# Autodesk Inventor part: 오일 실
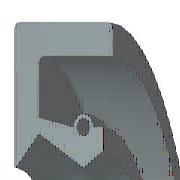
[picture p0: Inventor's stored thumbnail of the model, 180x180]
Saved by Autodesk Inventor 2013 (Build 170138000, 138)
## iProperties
IsCustomPart: 0
Created: 2009-02
Part Number: 오일 실
Material: 고무
Description: 오일-실
Document SubType Name: Modeling
Standard: KS B 2804
Designer: KYOUNG IL JANG
Standards Organization: KS
Language: ko-KR
Size Designation: D - 20 32 8
Categories: <MemberInstance><Categories><Category DisplayName="샤프트 부품" InternalName="7f7aeb1f-a693-4053-b835-cee3144e0d98" Mnemonic="SHFT"><Category DisplayName="실링" Intern
Density: 0.93 g/cm^3
Mass: 2.19344 g
Surface Area: 31.4782 cm^2
Volume: 2.35853 cm^3
Author: KYOUNG IL JANG
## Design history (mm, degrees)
revolve "본체" stored, may be unused: angle "d17" = 90 deg
revolve "스프링1" stored, may be unused: angle "d18" = 90 deg
body "Solid1"
sketch "스케치1"
  geometry: L1 (0, 16)-(8, 16); L2 (8, 14.25)-(1.75, 14.25); L3 (1.75, 11.75)-(4.9, 10); L4 (4.9, 10)-(0, 10); L5 (0, 0)-(9.586, 0) reference; L6 (4.9, 10)-(6.3, 10.875); L7 (0, 18)-(0, -3) reference; L8 (-1.941, 0)-(11.507, 0) reference; L9 (4.2, 12.1)-(1.75, 12.71); L10 (1.75, 12.71)-(1.75, 14.25); L11 (0, 16)-(0, 10.088); L12 (4.9, 10)-(0, 10); L13 (1.75, 11.75)-(0.152, 10.028); L14 (8, 16)-(8, 14.25); L15 (5.6, 12.1)-(6.3, 12.1); L16 (6.3, 12.1)-(6.3, 10.875); C1 r 0.455 at (4.9, 12.1); A1 r 0.7 centre (4.9, 12.1) between (5.6, 12.1) and (4.2, 12.1); A2 r 0.088 centre (0.088, 10.088) between (0, 10.088) and (0.152, 10.028); 1 further point
  constraints: 28 end point, 5 horizontal alignment, 5 point on line, 4 point on circle, 4 vertical alignment, 3 centre point, 3 tangent, 2 collinear, 2 horizontal, 2 perpendicular, 1 coincident, 1 parallel
  dimensions: "d0" = 32 diameter of L1 L5 (= SD2); "d1" = 1.75 distance of L1.end L2.start (= SD); "d2" = 0.91 diameter of C1 (= SPDI); "d3" = 1.4 diameter of A1 (= SPDA); "d4" = 20 diameter of L3.end L5 (= NND); "d5" = 23.5 diameter of L3.start L5 (= TKDM); "d7" = 25.42 diameter of L9.end L5 (= TKDM + 0.24 x SWDT); "d8" = 1.75 distance between parallel lines of L11 L10 (= SD); "d9" = 4.9 distance from line of L11 C1.centre (= SPDST); "d10" = 24.2 diameter of C1.centre L5 (= HLDM); "d11" = 0.0875 radius of A2 (= 0.25 x LAB); "d12" = 6.3 distance between parallel lines of L11 L16 (= SDI); "d13" = 21.75 diameter of L6.end L5 (= ABDM); "d14" = 8 distance from line of L11 L1.end (= SWDT)
fillet "모깎기1" dims "d6" = 0.3 (= RR)
other parameters: "SD2" = 32 [user parameter; used in 1 equation term], "SWDT" = 8 [user parameter; used in 2 equation terms], "RR" = 0.3 [user parameter; used in 1 equation term], "SD" = 1.75 [user parameter; used in 2 equation terms], "NND" = 20 [user parameter; used in 1 equation term], "SPDA" = 1.4 [user parameter; used in 1 equation term], "SPDI" = 0.91 [user parameter; used in 1 equation term], "TKDM" = 23.5 [user parameter; used in 2 equation terms], "HLDM" = 24.2 [user parameter; used in 1 equation term], "ABDM" = 21.75 [user parameter; used in 1 equation term], "SDI" = 6.3 [user parameter; used in 1 equation term], "SPDST" = 4.9 [user parameter; used in 1 equation term], "LAB" = 0.35 [user parameter; used in 1 equation term], "d15" = 0, "d16" = 0, "d19" = 0
